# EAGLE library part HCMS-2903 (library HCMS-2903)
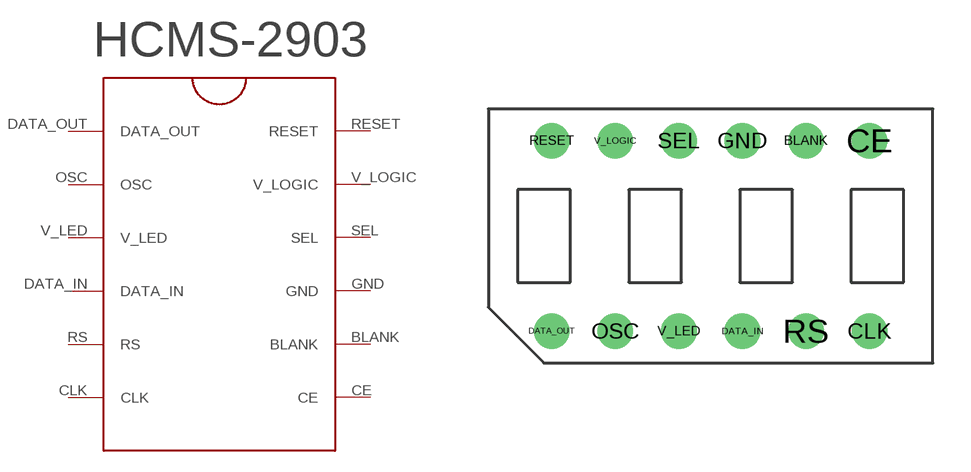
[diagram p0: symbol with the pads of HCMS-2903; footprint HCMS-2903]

Designator prefix -

## HCMS-2903  [HCMS-2903]
BLANK  BLANK
CE  CE
CLK  CLK
DATA_IN  DATA_IN
DATA_OUT  DATA_OUT
GND  GND
OSC  OSC
RESET  RESET
RS  RS
SEL  SEL
V_LED  V_LED
V_LOGIC  V_LOGIC

## Footprint HCMS-2903 (pad centres in mm)
drill 0.762 pad 1.422 round: BLANK 3.81,3.81; CE 6.35,3.81; CLK 6.35,-3.81; DATA_IN 1.27,-3.81; DATA_OUT -6.35,-3.81; GND 1.27,3.81; OSC -3.81,-3.81; RESET -6.35,3.81; RS 3.81,-3.81; SEL -1.27,3.81; V_LED -1.27,-3.81; V_LOGIC -3.81,3.81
